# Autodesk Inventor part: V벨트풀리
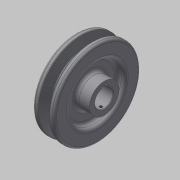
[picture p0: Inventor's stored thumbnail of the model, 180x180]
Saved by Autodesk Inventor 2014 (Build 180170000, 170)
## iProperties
Created: 2015-11
Part Number: V벨트풀리
Material: 강철, 탄소
Document SubType Name: Modeling
Designer: mduedu
Density: 1 g/cm^3
Appearance: 기본값
Author: mduedu
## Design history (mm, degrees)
sketch "스케치1"
  geometry: L1 (-9.5, 0)-(9.5, 0); L2 (0, 0)-(0, 37.7); L3 (-4.825, 37.7)-(-9.5, 37.7); L4 (-9.5, 37.7)-(-9.5, 0); L5 (0, 28.7)-(-2.074, 28.7); L6 (-2.074, 28.7)-(-4.825, 37.7); L7 (4.825, 37.7)-(9.5, 37.7); L8 (9.5, 37.7)-(9.5, 0); L9 (0, 28.7)-(2.074, 28.7); L10 (2.074, 28.7)-(4.825, 37.7); L11 (-9.5, 35)-(9.5, 35); 3 further points
  constraints: 22 end point, 7 point on line, 4 perpendicular, 3 symmetric about line, 1 coincident, 1 horizontal, 1 horizontal alignment, 1 midpoint, 1 vertical
  dimensions: "d0" = 19 distance of L1.start L1.end; "d2" = 75.4 diameter of L2.end L1 (derived); "d3" = 34 deg angle of L10 L6; "d4" = 6.3 distance between parallel lines of L11 L9; "d5" = 2.7 distance between parallel lines of L7 L11; "d6" = 8 distance of point (4, 35) point (-4, 35); "d7" = 70 diameter of L11 L1
revolve "회전1" sketch "스케치1" stored, may be unused: angle "d8" = 90 deg
sketch "스케치2"
  geometry: C1 r 24 at (0, 0); C2 r 13 at (0, 0); 1 further point
  constraints: 2 centre point, 2 coincident
  dimensions: "d9" = 48 diameter of C1; "d10" = 26 diameter of C2
extrude "돌출1" cut sketch "스케치2" distance "d11" = 6; taper "d12" = 0 deg
extrude "돌출3" join sketch "스케치2" distance "d37" = 6; taper "d38" = 0 deg
fillet "모깎기1" dims "d13" = 3
fillet "모깎기2" dims "d14" = 3
fillet "모깎기3" dims "d15" = 1, "d16" = 0.5, "d17" = 2
hole "구멍1" diameter "d20" = 16; stored, may be unused: countersink angle "d24" = 90 deg, drill point angle "d26" = 118 deg; dims "d21" = 6, "d22" = 4, "d23" = 2, "d25" = 8, "d53" = 10, "d54" = 10
sketch "스케치3"
  geometry: L1 (-2.5, 0)-(2.5, 0); L2 (2.5, 0)-(2.5, 10.3); L3 (2.5, 10.3)-(-2.5, 10.3); L4 (-2.5, 10.3)-(-2.5, 0); 2 further points
  constraints: 8 end point, 2 parallel, 1 coincident, 1 horizontal, 1 midpoint, 1 perpendicular
  dimensions: "d27" = 5 distance of L2.end L3.end; "d29" = 10.3 distance of L3.end L1.start
extrude "돌출2" cut sketch "스케치3" stored distance "d30" = 6; taper "d31" = 0 deg
node "작업 평면1"
sketch "스케치4"
  geometry: L1 (19, -27)-(19, 27) reference; 2 further points
  constraints: 1 horizontal alignment
  dimensions: "d52" = 22 distance from line of L1 point (-3, 0)
hole "구멍2" sketch "스케치4" at (-3, 0) diameter "d42" = 2.459; stored, may be unused: countersink angle "d46" = 90 deg, drill point angle "d48" = 118 deg; dims "d43" = 6, "d44" = 4, "d45" = 2, "d47" = 8
chamfer "모따기3" distance "d58" = 0.5; stored, may be unused: second distance "d59" = 2, angle "d60" = 45 deg
node "솔리드1"
mirror "대칭1"
